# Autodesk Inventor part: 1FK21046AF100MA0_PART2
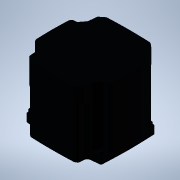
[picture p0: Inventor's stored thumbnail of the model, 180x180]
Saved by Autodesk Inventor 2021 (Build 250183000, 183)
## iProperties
Created: 2025-04
Part Number: 1FK21046AF100MA0_PART2
Material: Generic
Catalog Web Link: www.3dfindit.com
Description: -Servo synchronous motor
Document SubType Name: Modeling
Designer: psAdmin
Mass: 372.123 g
Surface Area: 313.117 cm^2
Volume: 372.123 cm^3
Density: 1 g/cm^3
Appearance: PSOLRGB-38-46-56
Category: PARTsolutions
Title: 1FK21046AF100MA0_PART2
Author: Cadenas PARTsolutions
Comments: Servo synchronous motor
Sending System: PARTsolutions
Preprocessor: ST-DEVELOPER v19.3
PSOL_IDENT_0: {$CADENAS_DATA/23d-libs/siemens_ag/_cat_/4f/2b/1fk21046af100ma0.prj},213 {VTYP=3D},{NB=1FK21046AF100
PSOL_IDENT_1: MA0_PART2},{LINA=1FK21046AF100MA0_PART2},{NN=1FK21046AF100MA0_PART2},{NOPRJ=TRUE},{DATE=19.08.2025 1
PSOL_IDENT_2: 4:00:37},{GEOMDATE=30.07.2025 02:01:06},{VERSION=},{LINEID=10},{WBVAR=},{WBNUMERIC=}  {NB=1FK21046AF
PSOL_IDENT_3: 100MA0_PART2},{LINA=1FK21046AF100MA0_PART2},{KT=DUMMY},{PREVIEW=../../../_pool_/cb/72/p_d211_xx_0043
PSOL_IDENT_4: 4j.png},{DESCSHORT=SIMOTICS S-1FK2 HD, SINAMICS S210 3AC 400V-480V, 3.2 Nm, 3000 rpm},{DESCLONG=SIMO
PSOL_IDENT_5: TICS S-1FK2 HD servo motor M0=3.2 Nm; PN = 1 kW at nN=3000 rpm (380-480 V); PN = 0.5 kW at nN=1500 r
PSOL_IDENT_6: pm (200-240 V); with holding brake; degree of protection IP64; cylindrical shaft D19x40mm; absolute
PSOL_IDENT_7: encoder 22-bit + 12-bit multiturn (encoder AM22DQC); with OCC interface; plug size M17, rotatable; S
PSOL_IDENT_8: IMOTICS S-1FK2 servomotorfor a wide range of uses in industrial environments. SIMOTICS S‑1FK2 servom
PSOL_IDENT_9: otors are compact synchronous motors with a high dynamic performance that set themselves apart as a
PSOL_IDENT_10: result of their high power density, degree of protection and overload capability. The motors are ava
PSOL_IDENT_11: ilable in two variants: as High Dynamic variant (highest dynamic performance as a result of the low
PSOL_IDENT_12: intrinsic moment of inertia for applications demanding a high dynamic performance with low moved mas
PSOL_IDENT_13: ses) - and as Compact variant (precise and stable closed-loop control for medium up to large moved m
PSOL_IDENT_14: asses as a result of a medium intrinsic moment of inertia). SIMOTICSS‑1FK2 servomotors fully exploit
PSOL_IDENT_15: their strengths in a system with the SINAMICSS210 frequency converter and simple connection using t
PSOL_IDENT_16: he one cable connection (OCC). Advantages include the short control and positioning times, fast and
PSOL_IDENT_17: precise correction of disturbing quantities as well as stable control with a high dynamic performanc
PSOL_IDENT_18: e. The servo motors can be configured to address a wide range of requirements. For example with and
PSOL_IDENT_19: without holding brake, IP64 or IP65 degree of protection, singleturn or multiturn absolute encoders
PSOL_IDENT_20: - to name just a few. Further, the servomotors are available in different shaft heights extending fr
PSOL_IDENT_21: om 20 to 100. A shaft sealing ring is available to achieve an IP65 degree of protection and for subs
PSOL_IDENT_22: equent mounting at the motor or as spare part. SIMOTICS - the optimum motor for each and every motio
PSOL_IDENT_23: n control application.},{INTNO=195125049673},{SUPPLIERALTNO=1FK2104-6AF10-0MA0},{MANUID=1FK21046AF10
PSOL_IDENT_24: 0MA0},{MANUNAME=Siemens},{MANUTYPEDESC=Synchronous motor 1FK2-HD 3.2 NM},{AAU732=SIMOTICS},{AAO057=S
PSOL_IDENT_25: -1FK2},{AAU734=SIMOTICS S-1FK2 HD servo motor M0=3.2 Nm; PN = 1 kW at nN=3000 rpm (380-480 V); PN =
PSOL_IDENT_26: 0.5 kW at nN=1500 rpm (200-240 V); with holding brake; degree of protection IP64; cylindrical shaft
PSOL_IDENT_27: D19x40mm; absolute encoder 22-bit + 12-bit multiturn (encoder AM22DQC); with OCC interface; plug siz
PSOL_IDENT_28: e M17, rotatable;},{AAW338=Synchronous motor 1FK2-HD 3.2 NM},{AAO742=SIMOTICS},{AAO663=4042948694534
PSOL_IDENT_29: },{NOCUPEROU=1},{PRICEQUANTITY=1},{QUANTITYMIN=1},{QUANTITYINT=1},{CTN=85015220},{COO=DE},{AAO676=1F
PSOL_IDENT_30: K2104-6AF10-0MA0},{AAO677=Siemens AG},{ORDERUNIT=C62},{CONTENTUNIT=C62}
NB: 1FK21046AF100MA0_PART2
NT: Servo synchronous motor
NBSYN: $MANUID._PART2
LINA: 1FK21046AF100MA0_PART2
CATALOG: SIEMENS
PREVIEW: ../../../_pool_/cb/72/p_d211_xx_00434j.png
DESCSHORT: SIMOTICS S-1FK2 HD, SINAMICS S210 3AC 400V-480V, 3.2 Nm, 3000 rpm
DESCLONG: SIMOTICS S-1FK2 HD servo motor M0=3.2 Nm; PN = 1 kW at nN=3000 rpm (380-480 V); PN = 0.5 kW at nN=1500 rpm (200-240 V); with holding brake; degree of protection
INTNO: 195125049673
SUPPLIERALTNO: 1FK2104-6AF10-0MA0
MANUID: 1FK21046AF100MA0
MANUNAME: Siemens
MANUTYPEDESC: Synchronous motor 1FK2-HD 3.2 NM
AAU732: SIMOTICS
AAO057: S-1FK2
AAU734: SIMOTICS S-1FK2 HD servo motor M0=3.2 Nm; PN = 1 kW at nN=3000 rpm (380-480 V); PN = 0.5 kW at nN=1500 rpm (200-240 V); with holding brake; degree of protection
AAW338: Synchronous motor 1FK2-HD 3.2 NM
AAO742: SIMOTICS
AAO663: 4042948694534.0
NOCUPEROU: 1
PRICEQUANTITY: 1
QUANTITYMIN: 1
QUANTITYINT: 1
CTN: 85015220
COO: DE
ARTICLENO: 1FK21046AF100MA0_PART2
BOMINFO: 1FK21046AF100MA0_PART2
CREATOR: CADENAS GmbH
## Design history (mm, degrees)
feature "2025_04_17_14_59_39_0052"
body "Solid1"
